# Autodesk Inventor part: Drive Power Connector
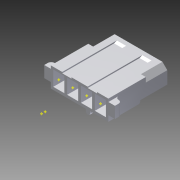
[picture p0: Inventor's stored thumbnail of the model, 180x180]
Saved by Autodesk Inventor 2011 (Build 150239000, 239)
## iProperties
Company: Autodesk Inc.
Created: 2006-09
Part Number: Drive Power Connector
Document SubType Name: Modeling
Designer: Autodesk Inc.
Density: 1 g/cm^3
Categories: <MemberInstance><Categories><Category DisplayName="" Mnemonic="CABLEANDHARNESS" InternalName="e4a7e005-5e42-4d16-b293-125e7f0d0512"><Category DisplayName="" Mne
Mass: 1.7319 g
Surface Area: 28.4781 cm^2
Volume: 1.7319 cm^3
Author: Autodesk Inc.
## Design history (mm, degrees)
feature "Base1"
sketch "Sketch1"
  geometry: L1 (-8.26, -6.29)-(-8.26, -7.37) reference; L2 (-8.26, -7.37)-(-4.08, -7.37) reference; L3 (-4.08, -7.37)-(-4.08, -6.94) reference; L4 (-4.08, -6.94)-(-0.68, -6.94) reference; L5 (-0.68, -7.37)-(-0.68, -6.94) reference; L6 (-0.68, -7.37)-(5.24, -7.37) reference; L7 (5.24, -7.37)-(5.24, -6.94) reference; L8 (5.24, -6.94)-(8.64, -6.94) reference; L9 (8.64, -7.37)-(8.64, -6.94) reference; L10 (8.64, -7.37)-(12.82, -7.37) reference; L11 (12.82, -7.37)-(12.82, -6.29) reference; L12 (12.82, -6.29)-(15.23, -6.29) reference; L13 (15.23, -6.29)-(15.23, -2.1) reference; L14 (12.82, -2.1)-(15.23, -2.1) reference; L15 (12.82, -2.1)-(12.82, 0) reference; L16 (0, 0)-(12.82, 0) reference; L17 (0, 0)-(0, 0.76) reference; L18 (-1.52, 0.76)-(-1.52, 0) reference; L19 (-8.26, 0)-(-1.52, 0) reference; L20 (-8.26, 0)-(-8.26, -2.1) reference; L21 (-10.67, -2.1)-(-8.26, -2.1) reference; L22 (-10.67, -6.29)-(-10.67, -2.1) reference; L23 (-10.67, -6.29)-(-8.26, -6.29) reference; L24 (-7.37, -1.02)-(-7.37, -6.52) reference; L25 (-3.31, -1.02)-(-7.37, -1.02) reference; L26 (-3.31, -6.52)-(-3.31, -1.02) reference; L27 (-7.37, -6.52)-(-3.31, -6.52) reference; L28 (-2.29, -1.02)-(-2.29, -6.52) reference; L29 (1.77, -1.02)-(-2.29, -1.02) reference; L30 (1.77, -6.52)-(1.77, -1.02) reference; L31 (-2.29, -6.52)-(1.77, -6.52) reference; L32 (2.79, -1.02)-(2.79, -6.52) reference; L33 (6.85, -1.02)-(2.79, -1.02) reference; L34 (6.85, -6.52)-(6.85, -1.02) reference; L35 (2.79, -6.52)-(6.85, -6.52) reference; L36 (7.87, -1.02)-(7.87, -6.52) reference; L37 (11.93, -1.02)-(7.87, -1.02) reference; L38 (11.93, -6.52)-(11.93, -1.02) reference; L39 (7.87, -6.52)-(11.93, -6.52) reference; C1 r 1.125 at (-5.34, -4.195) reference; C2 r 1.125 at (-0.26, -4.195) reference; C3 r 1.125 at (4.82, -4.195) reference; C4 r 1.125 at (9.9, -4.195) reference; A1 r 0.76 centre (-0.76, 0.76) between (0, 0.76) and (-1.52, 0.76) reference
node "1"
node "2"
node "3"
node "4"
workplane "Work Plane1"
workplane "Work Plane2"
sketch "Sketch2"
  geometry: L1 (4.82, -4.195)-(-0.26, -4.195); 1 further point
  constraints: 2 end point, 1 horizontal, 1 midpoint
workpoint "Work Point5"
sketch "Sketch3"
  geometry: 1 further point
workpoint "Work Point6"
body "Solid1"
other parameters: "d0" = 12.7, "d1" = 13.97
